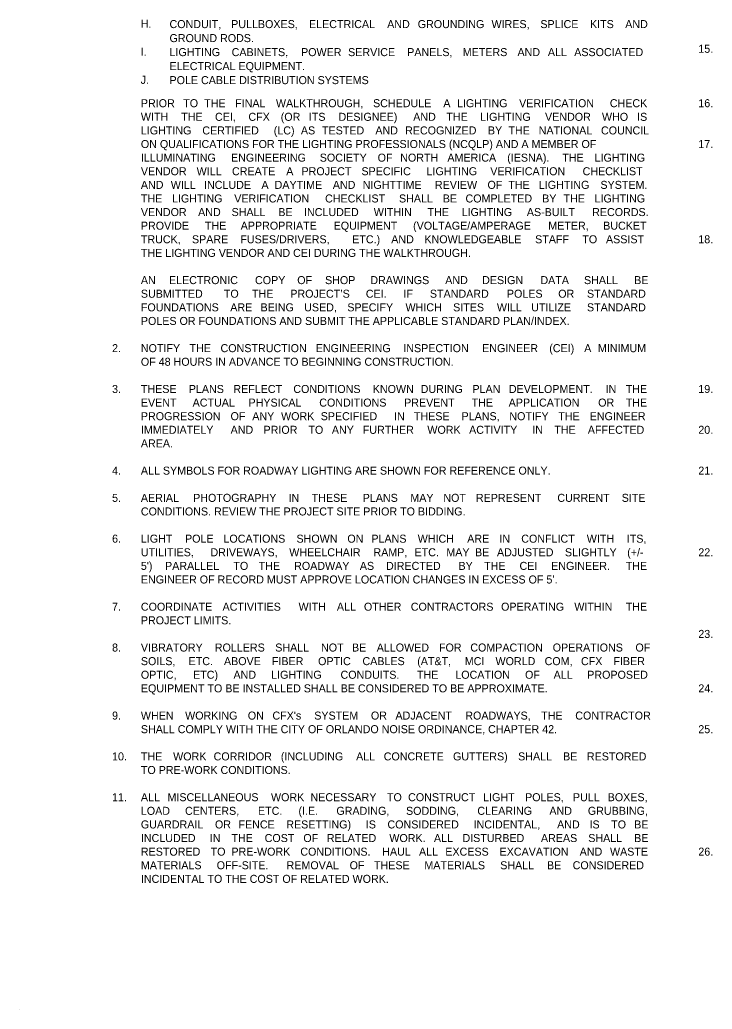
# Model space of a CAD drawing. Extents: x -55 to 2471539, y -90 to 3608906.
# Drawn here: x -55 to 551, y -90 to 775 of the extents above; entities that cross this region are included whole.
import ezdxf

# ---------------------------------------------------------------- set-up
doc = ezdxf.new("R2010")
doc.units = 0
doc.layers.add('TextMinor', color=7, linetype='Continuous')
doc.layers.add('XSCell', color=7, linetype='Continuous')

msp = doc.modelspace()

# ---------------------------------------------------------------- linework, layer by layer
at = {"layer": 'TextMinor'}
msp.add_line((-55, -90), (-55, -90), dxfattribs=at)

# ---------------------------------------------------------------- texts
at = {"layer": 'XSCell'}
for s, p in [('H.', (50.72, 768.23)), ('CONDUIT, ', (75.97, 767.96)), ('PULLBOXES, ', (129.89, 767.96)), ('ELECTRICAL ', (197.99, 767.96)), ('AND ', (266.35, 767.96)), ('GROUNDING ', (293.08, 767.96)), ('WIRES, ', (357.63, 767.96)), ('SPLICE ', (400.35, 767.96)), ('KITS ', (443.75, 767.96)), ('AND ', (474.57, 767.96)), ('GROUND RODS.', (75.97, 755.71)), ('15.', (538.51, 746.38)), ('I.', (50.72, 743.73)), ('LIGHTING ', (75.97, 743.46)), ('CABINETS, ', (130.32, 743.46)), ('POWER ', (191.04, 743.46)), ('SERVICE ', (232.19, 743.46)), ('PANELS, ', (283.88, 743.46)), ('METERS ', (332.46, 743.46)), ('AND ', (380.33, 743.46)), ('ALL ', (406.91, 743.46)), ('ASSOCIATED ', (429.97, 743.46)), ('ELECTRICAL EQUIPMENT.', (75.97, 731.21)), ('J.', (50.72, 719.23)), ('POLE CABLE DISTRIBUTION SYSTEMS', (75.97, 718.96)), ('PRIOR ', (50.92, 698.78)), ('TO ', (87.97, 698.78)), ('THE ', (106.26, 698.78)), ('FINAL ', (133.38, 698.78)), ('WALKTHROUGH, ', (169.06, 698.78)), ('SCHEDULE ', (254.01, 698.78)), ('A ', (315.47, 698.78)), ('LIGHTING ', (327.43, 698.78)), ('VERIFICATION ', (381.77, 698.78)), ('CHECK ', (461.12, 698.78)), ('16.', (538.51, 698.78)), ('WITH ', (50.92, 686.88)), ('THE ', (86.21, 686.88)), ('CEI, ', (115.75, 686.88)), ('CFX ', (145, 686.88)), ('(OR ', (173.26, 686.88)), ('ITS ', (197.82, 686.88)), ('DESIGNEE) ', (223.77, 686.88)), ('AND ', (289.13, 686.88)), ('THE ', (318.13, 686.88)), ('LIGHTING ', (347.67, 686.88)), ('VENDOR ', (404.44, 686.88)), ('WHO ', (454.24, 686.88)), ('IS ', (484.99, 686.88)), ('LIGHTING ', (50.92, 674.98)), ('CERTIFIED ', (104.66, 674.98)), ('(LC) ', (167.14, 674.98)), ('AS ', (190.89, 674.98)), ('TESTED ', (209.32, 674.98)), ('AND ', (256.04, 674.98)), ('RECOGNIZED ', (282.02, 674.98)), ('BY ', (354.46, 674.98)), ('THE ', (372.41, 674.98)), ('NATIONAL ', (398.92, 674.98)), ('COUNCIL ', (453.39, 674.98)), ('ON QUALIFICATIONS FOR THE LIGHTING PROFESSIONALS (NCQLP) AND A MEMBER OF ', (50.92, 663.08)), ('17.', (538.51, 663.08)), ('ILLUMINATING ', (50.92, 651.18)), ('ENGINEERING ', (129.76, 651.18)), ('SOCIETY ', (207.39, 651.18)), ('OF ', (258.02, 651.18)), ('NORTH ', (277.76, 651.18)), ('AMERICA ', (319.04, 651.18)), ('(IESNA). ', (371.35, 651.18)), ('THE ', (419.56, 651.18)), ('LIGHTING ', (447.79, 651.18)), ('VENDOR ', (50.92, 639.28)), ('WILL ', (99.69, 639.28)), ('CREATE ', (130.61, 639.28)), ('A ', (178.05, 639.28)), ('PROJECT ', (191.4, 639.28)), ('SPECIFIC ', (243.88, 639.28)), ('LIGHTING ', (300.8, 639.28)), ('VERIFICATION ', (356.54, 639.28)), ('CHECKLIST ', (437.29, 639.28)), ('AND ', (50.92, 627.38)), ('WILL ', (77.06, 627.38)), ('INCLUDE ', (106.15, 627.38)), ('A ', (156.37, 627.38)), ('DAYTIME ', (167.89, 627.38)), ('AND ', (218.8, 627.38)), ('NIGHTTIME ', (244.95, 627.38)), ('REVIEW ', (308.14, 627.38)), ('OF ', (354.11, 627.38)), ('THE ', (372.31, 627.38)), ('LIGHTING ', (399, 627.38)), ('SYSTEM. ', (452.91, 627.38)), ('THE ', (50.92, 615.48)), ('LIGHTING ', (78.14, 615.48)), ('VERIFICATION ', (132.59, 615.48)), ('CHECKLIST ', (212.05, 615.48)), ('SHALL ', (276.7, 615.48)), ('BE ', (315.01, 615.48)), ('COMPLETED ', (334.87, 615.48)), ('BY ', (401.91, 615.48)), ('THE ', (420.57, 615.48)), ('LIGHTING ', (447.79, 615.48)), ('VENDOR ', (50.92, 603.58)), ('AND ', (100.99, 603.58)), ('SHALL ', (130.26, 603.58)), ('BE ', (171.16, 603.58)), ('INCLUDED ', (193.6, 603.58)), ('WITHIN ', (254.63, 603.58)), ('THE ', (301.66, 603.58)), ('LIGHTING ', (331.48, 603.58)), ('AS-BUILT ', (388.52, 603.58)), ('RECORDS. ', (445.65, 603.58)), ('PROVIDE ', (50.92, 591.68)), ('THE ', (106.93, 591.68)), ('APPROPRIATE ', (138.23, 591.68)), ('EQUIPMENT ', (219.54, 591.68)), ('(VOLTAGE/AMPERAGE ', (289.04, 591.68)), ('METER, ', (407.26, 591.68)), ('BUCKET ', (455.29, 591.68)), ('TRUCK, ', (50.92, 579.78)), ('SPARE ', (95.61, 579.78)), ('FUSES/DRIVERS, ', (137.94, 579.78)), ('ETC.) ', (235.78, 579.78)), ('AND ', (269.92, 579.78)), ('KNOWLEDGEABLE ', (298.92, 579.78)), ('STAFF ', (395.78, 579.78)), ('TO ', (437.04, 579.78)), ('ASSIST ', (457.75, 579.78)), ('18.', (538.51, 579.78)), ('THE LIGHTING VENDOR AND CEI DURING THE WALKTHROUGH. ', (50.92, 567.88)), ('AN ', (50.92, 544.08)), ('ELECTRONIC ', (75.49, 544.08)), ('COPY ', (150.75, 544.08)), ('OF ', (187.7, 544.08)), ('SHOP ', (212.01, 544.08)), ('DRAWINGS ', (251.62, 544.08)), ('AND ', (317.13, 544.08)), ('DESIGN ', (349.39, 544.08)), ('DATA ', (400.39, 544.08)), ('SHALL ', (438.51, 544.08)), ('BE ', (482.39, 544.08)), ('SUBMITTED ', (50.92, 532.18)), ('TO ', (123.51, 532.18)), ('THE ', (148.15, 532.18)), ('PROJECT’S ', (181.63, 532.18)), ('CEI. ', (247.7, 532.18)), ('IF ', (280.58, 532.18)), ('STANDARD ', (303.72, 532.18)), ('POLES ', (371.09, 532.18)), ('OR ', (415.99, 532.18)), ('STANDARD ', (441.13, 532.18)), ('FOUNDATIONS ', (50.92, 520.28)), ('ARE ', (129.11, 520.28)), ('BEING ', (155.61, 520.28)), ('USED, ', (193.77, 520.28)), ('SPECIFY ', (231.5, 520.28)), ('WHICH ', (282.39, 520.28)), ('SITES ', (324.05, 520.28)), ('WILL ', (362.31, 520.28)), ('UTILIZE ', (392.36, 520.28)), ('STANDARD ', (441.13, 520.28)), ('POLES OR FOUNDATIONS AND SUBMIT THE APPLICABLE STANDARD PLAN/INDEX.', (50.92, 508.38)), ('2.', (25.72, 484.58)), ('NOTIFY ', (50.92, 484.58)), ('THE ', (93.4, 484.58)), ('CONSTRUCTION ', (120.59, 484.58)), ('ENGINEERING ', (203.89, 484.58)), ('INSPECTION ', (280.48, 484.58)), ('ENGINEER ', (349.42, 484.58)), ('(CEI) ', (408.14, 484.58)), ('A ', (438.69, 484.58)), ('MINIMUM ', (450.72, 484.58)), ('OF 48 HOURS IN ADVANCE TO BEGINNING CONSTRUCTION.', (50.92, 472.68)), ('3.', (25.72, 448.88)), ('THESE ', (50.92, 448.88)), ('PLANS ', (92.83, 448.88)), ('REFLECT ', (131.8, 448.88)), ('CONDITIONS ', (184.27, 448.88)), ('KNOWN ', (253.77, 448.88)), ('DURING ', (295.65, 448.88)), ('PLAN ', (340.92, 448.88)), ('DEVELOPMENT. ', (372.81, 448.88)), ('IN ', (457.44, 448.88)), ('THE ', (475.03, 448.88)), ('19.', (538.51, 448.88)), ('EVENT ', (50.92, 436.98)), ('ACTUAL ', (96.2, 436.98)), ('PHYSICAL ', (145.08, 436.98)), ('CONDITIONS ', (206.94, 436.98)), ('PREVENT ', (281.18, 436.98)), ('THE ', (340.2, 436.98)), ('APPLICATION ', (372.64, 436.98)), ('OR ', (450.92, 436.98)), ('THE ', (475.03, 436.98)), ('PROGRESSION ', (50.92, 425.08)), ('OF ', (129.35, 425.08)), ('ANY ', (148.35, 425.08)), ('WORK ', (173.54, 425.08)), ('SPECIFIED ', (208.2, 425.08)), ('IN ', (272.35, 425.08)), ('THESE ', (289.73, 425.08)), ('PLANS, ', (331.43, 425.08)), ('NOTIFY ', (373.24, 425.08)), ('THE ', (416.02, 425.08)), ('ENGINEER ', (443.5, 425.08)), ('IMMEDIATELY ', (50.92, 413.18)), ('AND ', (129.41, 413.18)), ('PRIOR ', (158.2, 413.18)), ('TO ', (197.46, 413.18)), ('ANY ', (217.96, 413.18)), ('FURTHER ', (244.99, 413.18)), ('WORK ', (301.5, 413.18)), ('ACTIVITY ', (338.01, 413.18)), ('IN ', (393.31, 413.18)), ('THE ', (412.53, 413.18)), ('AFFECTED ', (441.86, 413.18)), ('20.', (538.51, 413.18)), ('AREA.', (50.92, 401.28)), ('4.', (25.72, 377.48)), ('ALL SYMBOLS FOR ROADWAY LIGHTING ARE SHOWN FOR REFERENCE ONLY.', (50.92, 377.48)), ('21.', (538.51, 377.48)), ('5.', (25.72, 353.68)), ('AERIAL ', (50.92, 353.68)), ('PHOTOGRAPHY ', (96.65, 353.68)), ('IN ', (180.07, 353.68)), ('THESE ', (200.35, 353.68)), ('PLANS ', (244.95, 353.68)), ('MAY ', (286.61, 353.68)), ('NOT ', (315.49, 353.68)), ('REPRESENT ', (343.98, 353.68)), ('CURRENT ', (415.21, 353.68)), ('SITE ', (471.49, 353.68)), ('CONDITIONS. REVIEW THE PROJECT SITE PRIOR TO BIDDING.', (50.92, 341.78)), ('6.', (25.72, 317.98)), ('LIGHT ', (50.92, 317.98)), ('POLE ', (89.54, 317.98)), ('LOCATIONS ', (123.15, 317.98)), ('SHOWN ', (187.03, 317.98)), ('ON ', (231.54, 317.98)), ('PLANS ', (252.54, 317.98)), ('WHICH ', (293.07, 317.98)), ('ARE ', (336.35, 317.98)), ('IN ', (364.47, 317.98)), ('CONFLICT ', (383.63, 317.98)), ('WITH ', (440.93, 317.98)), ('ITS, ', (475.95, 317.98)), ('UTILITIES, ', (50.92, 306.08)), ('DRIVEWAYS, ', (111.78, 306.08)), ('WHEELCHAIR ', (180.68, 306.08)), ('RAMP, ', (254.36, 306.08)), ('ETC. ', (290.3, 306.08)), ('MAY ', (318.12, 306.08)), ('BE ', (343.19, 306.08)), ('ADJUSTED ', (362.4, 306.08)), ('SLIGHTLY ', (421.83, 306.08)), ('(+/- ', (476.32, 306.08)), ('22.', (538.51, 306.08)), ("5') ", (50.92, 294.18)), ('PARALLEL ', (72.07, 294.18)), ('TO ', (131.83, 294.18)), ('THE ', (153.99, 294.18)), ('ROADWAY ', (184.97, 294.18)), ('AS ', (242.43, 294.18)), ('DIRECTED ', (265.33, 294.18)), ('BY ', (328.73, 294.18)), ('THE ', (351.14, 294.18)), ('CEI ', (382.13, 294.18)), ('ENGINEER. ', (409.76, 294.18)), ('THE ', (475.03, 294.18)), ('ENGINEER OF RECORD MUST APPROVE LOCATION CHANGES IN EXCESS OF 5’.', (50.92, 282.28)), ('7.', (25.72, 258.48)), ('COORDINATE ', (50.92, 258.48)), ('ACTIVITIES ', (122.34, 258.48)), ('WITH ', (188.86, 258.48)), ('ALL ', (222.36, 258.48)), ('OTHER ', (246.03, 258.48)), ('CONTRACTORS ', (287.02, 258.48)), ('OPERATING ', (365.99, 258.48)), ('WITHIN ', (430.06, 258.48)), ('THE ', (475.03, 258.48)), ('PROJECT LIMITS.', (50.92, 246.58)), ('23.', (538.51, 234.68)), ('8.', (25.72, 222.78)), ('VIBRATORY ', (50.92, 222.78)), ('ROLLERS ', (115.6, 222.78)), ('SHALL ', (168.44, 222.78)), ('NOT ', (208.51, 222.78)), ('BE ', (235.59, 222.78)), ('ALLOWED ', (257.21, 222.78)), ('FOR ', (311.68, 222.78)), ('COMPACTION ', (339.05, 222.78)), ('OPERATIONS ', (411.16, 222.78)), ('OF ', (483.52, 222.78)), ('SOILS, ', (50.92, 210.88)), ('ETC. ', (92.67, 210.88)), ('ABOVE ', (123.59, 210.88)), ('FIBER ', (165.51, 210.88)), ('OPTIC ', (205.94, 210.88)), ('CABLES ', (244.74, 210.88)), ('(AT&T, ', (292.64, 210.88)), ('MCI ', (334.23, 210.88)), ('WORLD ', (361.13, 210.88)), ('COM, ', (404.06, 210.88)), ('CFX ', (435.87, 210.88)), ('FIBER ', (464.26, 210.88)), ('OPTIC, ', (50.92, 198.98)), ('ETC) ', (96.58, 198.98)), ('AND ', (131.91, 198.98)), ('LIGHTING ', (164.85, 198.98)), ('CONDUITS. ', (225.56, 198.98)), ('THE ', (292.46, 198.98)), ('LOCATION ', (325.94, 198.98)), ('OF ', (386.95, 198.98)), ('ALL ', (411.94, 198.98)), ('PROPOSED ', (441.35, 198.98)), ('EQUIPMENT TO BE INSTALLED SHALL BE CONSIDERED TO BE APPROXIMATE.', (50.92, 187.08)), ('24.', (538.51, 187.08)), ('9.', (25.72, 163.28)), ('WHEN ', (50.92, 163.28)), ('WORKING ', (89.63, 163.28)), ('ON ', (144.47, 163.28)), ("CFX's ", (166, 163.28)), ('SYSTEM ', (202.59, 163.28)), ('OR ', (252.13, 163.28)), ('ADJACENT ', (273.59, 163.28)), ('ROADWAYS, ', (334.69, 163.28)), ('THE ', (401.09, 163.28)), ('CONTRACTOR ', (430.88, 163.28)), ('SHALL COMPLY WITH THE CITY OF ORLANDO NOISE ORDINANCE, CHAPTER 42.', (50.92, 151.38)), ('25.', (538.51, 151.38)), ('10.', (25.72, 127.58)), ('THE ', (50.92, 127.58)), ('WORK ', (79.14, 127.58)), ('CORRIDOR ', (114.54, 127.58)), ('(INCLUDING ', (173.34, 127.58)), ('ALL ', (239.19, 127.58)), ('CONCRETE ', (263.34, 127.58)), ('GUTTERS) ', (323.94, 127.58)), ('SHALL ', (380.9, 127.58)), ('BE ', (420.21, 127.58)), ('RESTORED ', (441.07, 127.58)), ('TO PRE-WORK CONDITIONS.', (50.92, 115.68)), ('11.', (25.72, 91.88)), ('ALL ', (50.92, 91.88)), ('MISCELLANEOUS ', (74.2, 91.88)), ('WORK ', (164.73, 91.88)), ('NECESSARY ', (199.25, 91.88)), ('TO ', (266.17, 91.88)), ('CONSTRUCT ', (284.68, 91.88)), ('LIGHT ', (350.29, 91.88)), ('POLES, ', (386.99, 91.88)), ('PULL ', (428.81, 91.88)), ('BOXES, ', (459.25, 91.88)), ('LOAD ', (50.92, 79.98)), ('CENTERS, ', (89.55, 79.98)), ('ETC. ', (153.33, 79.98)), ('(I.E. ', (188.77, 79.98)), ('GRADING, ', (221.91, 79.98)), ('SODDING, ', (282.85, 79.98)), ('CLEARING ', (345.23, 79.98)), ('AND ', (408.25, 79.98)), ('GRUBBING, ', (441.91, 79.98)), ('GUARDRAIL ', (50.92, 68.08)), ('OR ', (115.72, 68.08)), ('FENCE ', (136.3, 68.08)), ('RESETTING) ', (178.12, 68.08)), ('IS ', (247.66, 68.08)), ('CONSIDERED ', (266.61, 68.08)), ('INCIDENTAL, ', (341.94, 68.08)), ('AND ', (414.99, 68.08)), ('IS ', (443.37, 68.08)), ('TO ', (462.31, 68.08)), ('BE ', (482.39, 68.08)), ('INCLUDED ', (50.92, 56.18)), ('IN ', (111.19, 56.18)), ('THE ', (130.13, 56.18)), ('COST ', (159.19, 56.18)), ('OF ', (193.05, 56.18)), ('RELATED ', (213.61, 56.18)), ('WORK. ', (268.26, 56.18)), ('ALL ', (307.24, 56.18)), ('DISTURBED ', (332.23, 56.18)), ('AREAS ', (400.86, 56.18)), ('SHALL ', (442.26, 56.18)), ('BE ', (482.39, 56.18)), ('RESTORED ', (50.92, 44.28)), ('TO ', (111.92, 44.28)), ('PRE-WORK ', (130.13, 44.28)), ('CONDITIONS. ', (190.4, 44.28)), ('HAUL ', (262, 44.28)), ('ALL ', (294.21, 44.28)), ('EXCESS ', (317.19, 44.28)), ('EXCAVATION ', (364.68, 44.28)), ('AND ', (434.74, 44.28)), ('WASTE ', (461.25, 44.28)), ('26.', (538.51, 44.28)), ('MATERIALS ', (50.92, 32.38)), ('OFF-SITE. ', (117.26, 32.38)), ('REMOVAL ', (178.36, 32.38)), ('OF ', (233.51, 32.38)), ('THESE ', (254.85, 32.38)), ('MATERIALS ', (298.89, 32.38)), ('SHALL ', (365.23, 32.38)), ('BE ', (406.14, 32.38)), ('CONSIDERED ', (428.6, 32.38)), ('INCIDENTAL TO THE COST OF RELATED WORK.', (50.92, 20.48))]:
    msp.add_text(s, height=7, dxfattribs=at).set_placement(p)

doc.saveas('drawing.dxf')
